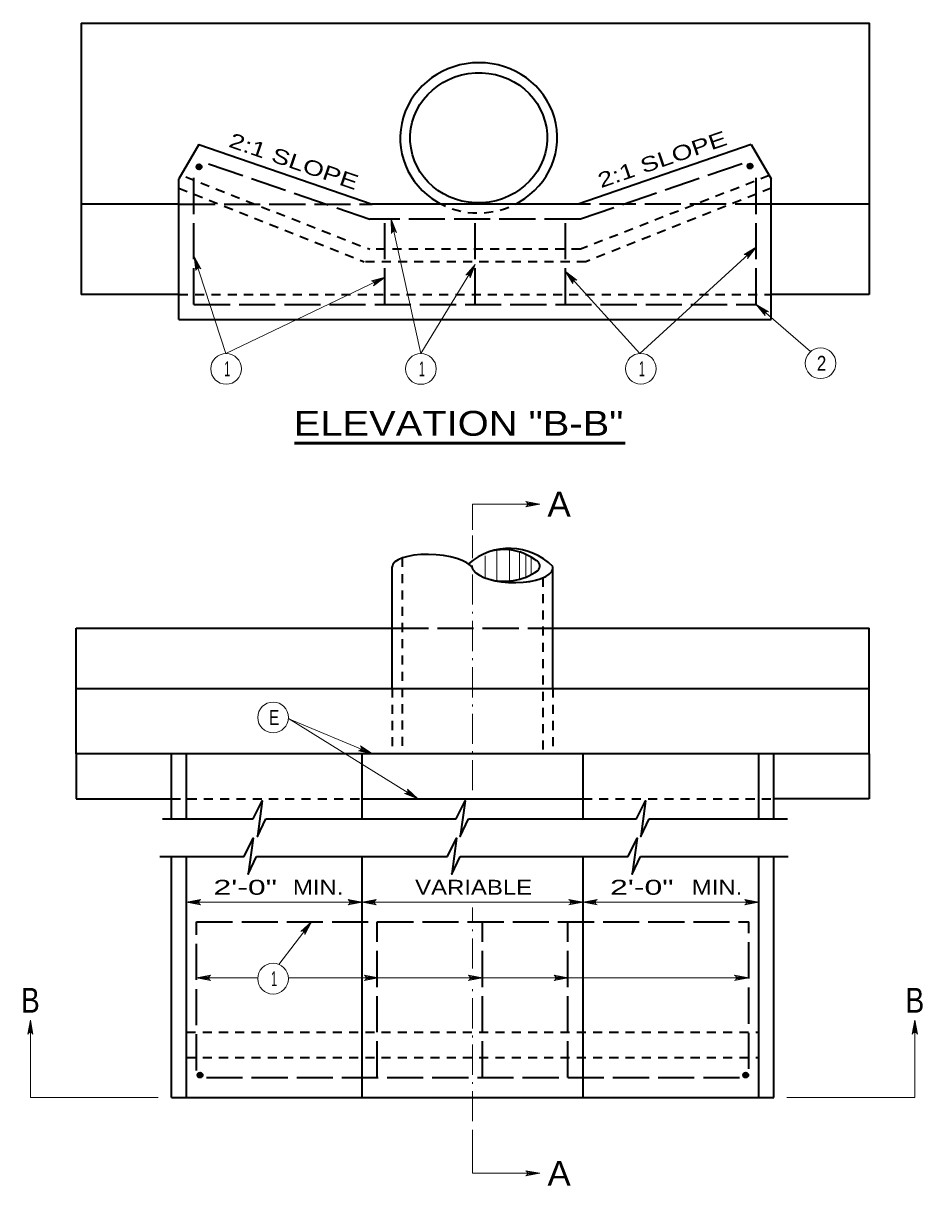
# Model space of a CAD drawing. Extents: x 2 to 114, y -129 to 32.
# Drawn here: x 1.8 to 61.5, y -49.3 to 27.9 of the extents above; entities that cross this region are included whole.
import ezdxf
from ezdxf.enums import TextEntityAlignment as Align

# ---------------------------------------------------------------- set-up
doc = ezdxf.new("R2010")
doc.units = 0
doc.header["$LTSCALE"] = 0.4
for name, pattern in [('DOT_DASHED', [7.7, 5, -1.2, 0.3, -1.2]), ('LONG_DASHED', [7.5, 6, -1.5]), ('SHORT_DASHED', [2.7, 1.5, -1.2])]:
    doc.linetypes.add(name, pattern=pattern)
for name, color, linetype, lineweight in [('1', 7, 'Continuous', 35), ('10', 7, 'Continuous', 13), ('12', 7, 'Continuous', 53), ('13', 7, 'Continuous', 25), ('6', 7, 'Continuous', 13)]:
    doc.layers.add(name, color=color, linetype=linetype, lineweight=lineweight)

msp = doc.modelspace()

# ---------------------------------------------------------------- linework, layer by layer
at = {"layer": '1'}
for p, q in [((5.5976, 27.8637), (5.5976, 9.8637)), ((13.4219, 19.8096), (12.0976, 17.5303)), ((13.4219, 19.8096), (24.9309, 15.8637)), ((50.1066, 19.8096), (38.5976, 15.8637)), ((50.1066, 19.8096), (51.4309, 17.5303)), ((12.0976, 8.197), (12.0976, 17.5303)), ((51.4309, 8.197), (51.4309, 17.5303)), ((12.0976, 15.8637), (5.5976, 15.8637)), ((38.7681, 15.8637), (24.9309, 15.8637)), ((57.9309, 15.8637), (51.4309, 15.8637)), ((51.4309, 9.8637), (51.4309, 14.8637)), ((12.0976, 9.8637), (5.5976, 9.8637)), ((57.9309, 9.8637), (51.4309, 9.8637)), ((12.0976, 8.197), (51.4309, 8.197)), ((26.2643, -16.2894), (26.2643, -8.1969)), ((31.6675, -8.4378), (31.5976, -8.3026)), ((36.9309, -16.2894), (36.9309, -8.1969)), ((5.2643, -16.2894), (5.2643, -12.2894)), ((5.2643, -12.2894), (26.2643, -12.2894)), ((36.9309, -12.2894), (57.9309, -12.2894)), ((57.9309, -16.2894), (57.9309, -12.2894)), ((5.2643, -16.2894), (57.9309, -16.2894)), ((5.2643, -20.6228), (5.2643, -16.2894)), ((57.9309, -20.6228), (57.9309, -16.2894)), ((11.5976, -20.6228), (5.2643, -20.6228)), ((5.2643, -20.6228), (5.2643, -23.6228)), ((11.5976, -24.9561), (11.5976, -20.6228)), ((51.5976, -20.6228), (11.5976, -20.6228)), ((12.5976, -24.9561), (12.5976, -20.6228)), ((24.2643, -24.9561), (24.2643, -20.6228)), ((38.9309, -24.9561), (38.9309, -20.6228)), ((50.5976, -24.9561), (50.5976, -20.6228)), ((51.5976, -24.9561), (51.5976, -20.6228)), ((57.9309, -20.6228), (51.5976, -20.6228)), ((57.9309, -20.6228), (57.9309, -23.6228)), ((5.2643, -23.6228), (11.5976, -23.6228)), ((24.2643, -23.6228), (38.9309, -23.6228)), ((24.2643, -23.6228), (38.9309, -23.6228)), ((57.9309, -23.6228), (51.5976, -23.6228)), ((10.999, -24.9561), (17.0348, -24.9561)), ((17.8594, -24.9561), (30.5059, -24.9561)), ((31.3306, -24.9561), (42.49, -24.9561)), ((43.3146, -24.9561), (52.5059, -24.9561)), ((10.8241, -27.4473), (16.4224, -27.4473)), ((11.5976, -43.4473), (11.5976, -27.4473)), ((12.5976, -43.4473), (12.5976, -27.4473)), ((17.2471, -27.4473), (29.9373, -27.4473)), ((24.2643, -43.4473), (24.2643, -27.4473)), ((30.762, -27.4473), (41.9214, -27.4473)), ((38.9309, -43.4473), (38.9309, -27.4473)), ((42.746, -27.4473), (52.5496, -27.4473)), ((50.5976, -43.4473), (50.5976, -27.4473)), ((51.5976, -43.4473), (51.5976, -27.4473)), ((11.5976, -43.4473), (51.5976, -43.4473))]:
    msp.add_line(p, q, dxfattribs=at)
at = {"layer": '1', "linetype": 'LONG_DASHED'}
for p, q in [((14.0701, 18.5302), (24.7643, 14.8637)), ((49.4889, 18.5407), (38.7643, 14.8637)), ((13.0976, 9.197), (13.0976, 17.7631)), ((50.4309, 9.197), (50.4309, 18.0603)), ((12.0976, 15.8637), (24.9309, 15.8637)), ((51.4309, 15.8637), (38.7681, 15.8637)), ((38.7643, 14.8637), (24.7643, 14.8637)), ((25.7643, 9.197), (25.7643, 14.8637)), ((31.7643, 9.197), (31.7643, 14.8637)), ((37.7643, 9.197), (37.7643, 14.8637)), ((13.0976, 9.197), (50.4309, 9.197)), ((26.2643, -12.2894), (36.9309, -12.2894)), ((13.2643, -31.7806), (49.9309, -31.7806)), ((13.2643, -41.642), (13.2643, -31.7806)), ((25.2643, -42.114), (25.2643, -31.7806)), ((32.2643, -42.114), (32.2643, -31.7806)), ((37.9309, -42.114), (37.9309, -31.7806)), ((49.9309, -41.5423), (49.9309, -31.7806)), ((13.9208, -42.114), (49.3179, -42.114))]:
    msp.add_line(p, q, dxfattribs=at)
at = {"layer": '1', "linetype": 'SHORT_DASHED'}
for p, q in [((51.3017, 17.7527), (38.7643, 12.8637)), ((12.548, 17.6583), (24.7643, 12.8637)), ((12.0976, 16.916), (24.4031, 12.0303)), ((51.4309, 16.916), (39.1254, 12.0303)), ((38.7643, 12.8637), (24.7643, 12.8637)), ((39.1254, 12.0303), (24.4031, 12.0303)), ((12.0976, 9.8637), (51.4309, 9.8637)), ((26.9309, -7.6253), (26.9309, -20.6228)), ((36.2643, -8.9469), (36.2643, -20.6228)), ((26.2643, -16.2894), (26.2643, -20.6228)), ((36.9309, -16.2894), (36.9309, -20.6228)), ((11.5976, -23.6228), (24.2643, -23.6228)), ((38.9309, -23.6228), (51.5976, -23.6228)), ((12.5976, -39.114), (50.5976, -39.114)), ((12.5976, -40.7806), (50.5976, -40.7806))]:
    msp.add_line(p, q, dxfattribs=at)
at = {"layer": '1'}
msp.add_lwpolyline([(5.5976, 27.8637), (57.9309, 27.8637), (57.9309, 9.8637)], dxfattribs=at)
for centre, radius in [((50.0237, 18.3857), 0.1667), ((13.4364, 18.3326), 0.1667), ((13.4364, 18.3326), 0.125), ((13.4364, 18.3326), 0.0833), ((13.4364, 18.3326), 0.0417), ((50.0237, 18.3857), 0.125), ((50.0237, 18.3857), 0.0833), ((50.0237, 18.3857), 0.0417), ((13.5012, -41.9572), 0.1667), ((13.5012, -41.9572), 0.125), ((13.5012, -41.9572), 0.0833), ((13.5012, -41.9572), 0.0417), ((49.7375, -41.9572), 0.1667), ((49.7375, -41.9572), 0.125), ((49.7375, -41.9572), 0.0833), ((49.7375, -41.9572), 0.0417)]:
    msp.add_circle(centre, radius, dxfattribs=at)
for centre, radius, start, end in [((34.034, -11.1003), 4.1015, 45.06377, 131.36728), ((33.6786, -10.6189), 3.5429, 52.80449, 103.76963), ((33.7104, -5.3561), 3.82, 253.17764, 305.12429), ((35.6608, -8.1634), 0.3998, 313.54691, 66.48149)]:
    msp.add_arc(centre, radius, start, end, dxfattribs=at)
for centre, major_axis, ratio, start_param, end_param in [((32.0041, 20.2567), (-5.2068, -0.2894), 0.95662, 2.0626148, 7.2453181), ((28.957, -8.3542), (2.6927, -0.1573), 0.351288, 0.2186166, 3.1826279), ((34.2678, -8.2376), (2.6702, -0.0408), 0.385255, 3.3768954, 6.2157676)]:
    msp.add_ellipse(centre, major_axis=major_axis, ratio=ratio, start_param=start_param, end_param=end_param, dxfattribs=at)
msp.add_ellipse((32.0041, 20.2567), major_axis=(-4.5412, -0.2524), ratio=0.950261, dxfattribs=at)
at = {"layer": '1', "linetype": 'SHORT_DASHED'}
msp.add_ellipse((32.0041, 20.2567), major_axis=(-5.2068, -0.2894), ratio=0.95662, start_param=0.9621318, end_param=2.0626168, dxfattribs=at)
at = {"layer": '10'}
for p, q in [((15.2195, 5.9356), (13.1063, 12.3876)), ((42.7045, 5.9313), (50.4309, 13.0053)), ((15.2104, 5.9313), (25.7913, 11.0041)), ((42.709, 5.9354), (37.7643, 11.39)), ((50.4309, 9.197), (54.0407, 6.068)), ((31.5976, -4.0563), (36.0703, -4.0563)), ((31.5976, -5.7715), (31.5976, -4.0563)), ((19.3702, -18.2923), (27.9716, -23.6164)), ((19.4419, -18.3367), (24.9465, -20.6262)), ((18.722, -34.6078), (20.8929, -31.7806)), ((13.2643, -35.5077), (17.3297, -35.5077)), ((19.3657, -35.5077), (49.9309, -35.5077)), ((2.231, -43.4473), (2.231, -38.3153)), ((60.9642, -43.4473), (60.9642, -38.3153)), ((10.7147, -43.4473), (2.231, -43.4473)), ((60.9642, -43.4473), (52.4661, -43.4473)), ((31.5976, -48.476), (31.5976, -45.5984)), ((31.5976, -48.476), (36.0703, -48.476))]:
    msp.add_line(p, q, dxfattribs=at)
at = {"layer": '10', "linetype": 'DOT_DASHED'}
for p, q in [((31.5976, -23.0458), (31.5976, -6.1362)), ((31.5976, -34.8878), (31.5976, -30.8354)), ((31.5976, -45.0148), (31.5976, -36.128))]:
    msp.add_line(p, q, dxfattribs=at)
at = {"layer": '10'}
for points in [[(26.182, 14.8538), (28.1659, 5.9313), (31.7731, 11.8462)], [(26.182, 14.8538), (26.5549, 13.9819), (26.4908, 14.0412), (26.4217, 14.0637), (26.3584, 14.0606), (26.2997, 14.0366), (26.2467, 13.9869), (26.2137, 13.906), (26.182, 14.8538), (26.2467, 13.9869), (26.2997, 14.0366), (26.182, 14.8538), (26.3584, 14.0606), (26.4217, 14.0637), (26.182, 14.8538), (26.4908, 14.0412)], [(13.1063, 12.3876), (13.5625, 11.5562), (13.4928, 11.609), (13.4219, 11.6247), (13.3592, 11.6154), (13.3031, 11.5858), (13.2552, 11.5311), (13.2303, 11.4474), (13.1063, 12.3876), (13.2552, 11.5311), (13.3031, 11.5858), (13.1063, 12.3876), (13.3592, 11.6154), (13.4219, 11.6247), (13.1063, 12.3876), (13.4928, 11.609)], [(50.4309, 13.0053), (49.8615, 12.247), (49.8809, 12.3322), (49.866, 12.4033), (49.8317, 12.4566), (49.7816, 12.4955), (49.712, 12.5166), (49.6255, 12.5048), (50.4309, 13.0053), (49.712, 12.5166), (49.7816, 12.4955), (50.4309, 13.0053), (49.8317, 12.4566), (49.866, 12.4033), (50.4309, 13.0053), (49.8809, 12.3322)], [(31.7731, 11.8462), (31.437, 10.9594), (31.4319, 11.0467), (31.3978, 11.1108), (31.35, 11.1525), (31.2911, 11.1759), (31.2184, 11.1768), (31.1386, 11.1414), (31.7731, 11.8462), (31.2184, 11.1768), (31.2911, 11.1759), (31.7731, 11.8462), (31.35, 11.1525), (31.3978, 11.1108), (31.7731, 11.8462), (31.4319, 11.0467)], [(25.7913, 11.0041), (25.0263, 10.4436), (25.0696, 10.5195), (25.076, 10.5918), (25.0586, 10.6528), (25.0219, 10.7046), (24.9615, 10.7449), (24.8752, 10.7587), (25.7913, 11.0041), (24.9615, 10.7449), (25.0219, 10.7046), (25.7913, 11.0041), (25.0586, 10.6528), (25.076, 10.5918), (25.7913, 11.0041), (25.0696, 10.5195)], [(37.7643, 11.39), (38.5198, 10.8168), (38.4346, 10.8366), (38.3635, 10.8221), (38.31, 10.788), (38.2709, 10.7381), (38.2494, 10.6687), (38.2608, 10.5821), (37.7643, 11.39), (38.2494, 10.6687), (38.2709, 10.7381), (37.7643, 11.39), (38.31, 10.788), (38.3635, 10.8221), (37.7643, 11.39), (38.4346, 10.8366)], [(50.4309, 9.197), (51.2497, 8.7185), (51.1628, 8.728), (51.0939, 8.705), (51.0449, 8.6648), (51.012, 8.6106), (50.9991, 8.5391), (51.0208, 8.4544), (50.4309, 9.197), (50.9991, 8.5391), (51.012, 8.6106), (50.4309, 9.197), (51.0449, 8.6648), (51.0939, 8.705), (50.4309, 9.197), (51.1628, 8.728)], [(36.0703, -4.0563), (35.1382, -4.2311), (35.21, -4.1813), (35.2471, -4.1188), (35.2578, -4.0563), (35.2471, -3.9938), (35.21, -3.9313), (35.1382, -3.8815), (36.0703, -4.0563), (35.21, -3.9313), (35.2471, -3.9938), (36.0703, -4.0563), (35.2578, -4.0563), (35.2471, -4.1188), (36.0703, -4.0563), (35.21, -4.1813)], [(24.9465, -20.6262), (24.0188, -20.4296), (24.1042, -20.4112), (24.1624, -20.3677), (24.1963, -20.3141), (24.2104, -20.2523), (24.2002, -20.1804), (24.153, -20.1069), (24.9465, -20.6262), (24.2002, -20.1804), (24.2104, -20.2523), (24.9465, -20.6262), (24.1963, -20.3141), (24.1624, -20.3677), (24.9465, -20.6262), (24.1042, -20.4112)], [(27.9716, -23.6164), (27.087, -23.2745), (27.1743, -23.2699), (27.2387, -23.2363), (27.2807, -23.1888), (27.3045, -23.13), (27.3059, -23.0574), (27.271, -22.9773), (27.9716, -23.6164), (27.3059, -23.0574), (27.3045, -23.13), (27.9716, -23.6164), (27.2807, -23.1888), (27.2387, -23.2363), (27.9716, -23.6164), (27.1743, -23.2699)], [(12.5976, -30.4844), (13.5297, -30.3096), (13.4579, -30.3594), (13.4208, -30.4219), (13.4101, -30.4844), (13.4208, -30.5469), (13.4579, -30.6094), (13.5297, -30.6591), (12.5976, -30.4844), (13.4579, -30.6094), (13.4208, -30.5469), (12.5976, -30.4844), (13.4101, -30.4844), (13.4208, -30.4219), (12.5976, -30.4844), (13.4579, -30.3594)], [(12.5976, -30.4844), (24.2643, -30.4844), (38.9309, -30.4844), (50.5976, -30.4844)], [(24.2643, -30.4844), (23.3322, -30.6591), (23.404, -30.6094), (23.4411, -30.5469), (23.4518, -30.4844), (23.4411, -30.4219), (23.404, -30.3594), (23.3322, -30.3096), (24.2643, -30.4844), (23.404, -30.3594), (23.4411, -30.4219), (24.2643, -30.4844), (23.4518, -30.4844), (23.4411, -30.5469), (24.2643, -30.4844), (23.404, -30.6094)], [(24.2643, -30.4844), (25.1963, -30.6591), (25.1245, -30.6094), (25.0875, -30.5469), (25.0768, -30.4844), (25.0875, -30.4219), (25.1245, -30.3594), (25.1963, -30.3096), (24.2643, -30.4844), (25.1245, -30.3594), (25.0875, -30.4219), (24.2643, -30.4844), (25.0768, -30.4844), (25.0875, -30.5469), (24.2643, -30.4844), (25.1245, -30.6094)], [(38.9309, -30.4844), (37.9989, -30.6591), (38.0707, -30.6094), (38.1077, -30.5469), (38.1184, -30.4844), (38.1077, -30.4219), (38.0707, -30.3594), (37.9989, -30.3096), (38.9309, -30.4844), (38.0707, -30.3594), (38.1077, -30.4219), (38.9309, -30.4844), (38.1184, -30.4844), (38.1077, -30.5469), (38.9309, -30.4844), (38.0707, -30.6094)], [(38.9309, -30.4844), (39.863, -30.6591), (39.7912, -30.6094), (39.7542, -30.5469), (39.7434, -30.4844), (39.7542, -30.4219), (39.7912, -30.3594), (39.863, -30.3096), (38.9309, -30.4844), (39.7912, -30.3594), (39.7542, -30.4219), (38.9309, -30.4844), (39.7434, -30.4844), (39.7542, -30.5469), (38.9309, -30.4844), (39.7912, -30.6094)], [(50.5976, -30.4844), (49.6655, -30.6591), (49.7374, -30.6094), (49.7744, -30.5469), (49.7851, -30.4844), (49.7744, -30.4219), (49.7374, -30.3594), (49.6655, -30.3096), (50.5976, -30.4844), (49.7374, -30.3594), (49.7744, -30.4219), (50.5976, -30.4844), (49.7851, -30.4844), (49.7744, -30.5469), (50.5976, -30.4844), (49.7374, -30.6094)], [(20.8929, -31.7806), (20.4639, -32.6263), (20.4681, -32.5391), (20.4411, -32.4716), (20.3981, -32.4251), (20.342, -32.3955), (20.2699, -32.3868), (20.1867, -32.4135), (20.8929, -31.7806), (20.2699, -32.3868), (20.342, -32.3955), (20.8929, -31.7806), (20.3981, -32.4251), (20.4411, -32.4716), (20.8929, -31.7806), (20.4681, -32.5391)], [(13.2643, -35.5077), (14.1963, -35.333), (14.1245, -35.3827), (14.0875, -35.4452), (14.0768, -35.5077), (14.0875, -35.5702), (14.1245, -35.6327), (14.1963, -35.6825), (13.2643, -35.5077), (14.1245, -35.6327), (14.0875, -35.5702), (13.2643, -35.5077), (14.0768, -35.5077), (14.0875, -35.4452), (13.2643, -35.5077), (14.1245, -35.3827)], [(25.3505, -35.5077), (24.4184, -35.6825), (24.4902, -35.6327), (24.5273, -35.5702), (24.538, -35.5077), (24.5273, -35.4452), (24.4902, -35.3827), (24.4184, -35.333), (25.3505, -35.5077), (24.4902, -35.3827), (24.5273, -35.4452), (25.3505, -35.5077), (24.538, -35.5077), (24.5273, -35.5702), (25.3505, -35.5077), (24.4902, -35.6327)], [(32.261, -35.5077), (31.3289, -35.6825), (31.4008, -35.6327), (31.4378, -35.5702), (31.4485, -35.5077), (31.4378, -35.4452), (31.4008, -35.3827), (31.3289, -35.333), (32.261, -35.5077), (31.4008, -35.3827), (31.4378, -35.4452), (32.261, -35.5077), (31.4485, -35.5077), (31.4378, -35.5702), (32.261, -35.5077), (31.4008, -35.6327)], [(37.9469, -35.5077), (37.0148, -35.6825), (37.0866, -35.6327), (37.1237, -35.5702), (37.1344, -35.5077), (37.1237, -35.4452), (37.0866, -35.3827), (37.0148, -35.333), (37.9469, -35.5077), (37.0866, -35.3827), (37.1237, -35.4452), (37.9469, -35.5077), (37.1344, -35.5077), (37.1237, -35.5702), (37.9469, -35.5077), (37.0866, -35.6327)], [(49.9309, -35.5077), (48.9989, -35.6825), (49.0707, -35.6327), (49.1077, -35.5702), (49.1184, -35.5077), (49.1077, -35.4452), (49.0707, -35.3827), (48.9989, -35.333), (49.9309, -35.5077), (49.0707, -35.3827), (49.1077, -35.4452), (49.9309, -35.5077), (49.1184, -35.5077), (49.1077, -35.5702), (49.9309, -35.5077), (49.0707, -35.6327)], [(2.231, -38.3153), (2.4058, -39.2474), (2.356, -39.1755), (2.2935, -39.1385), (2.231, -39.1278), (2.1685, -39.1385), (2.106, -39.1755), (2.0563, -39.2474), (2.231, -38.3153), (2.106, -39.1755), (2.1685, -39.1385), (2.231, -38.3153), (2.231, -39.1278), (2.2935, -39.1385), (2.231, -38.3153), (2.356, -39.1755)], [(60.9642, -38.3153), (61.1389, -39.2474), (61.0892, -39.1755), (61.0267, -39.1385), (60.9642, -39.1278), (60.9017, -39.1385), (60.8392, -39.1755), (60.7894, -39.2474), (60.9642, -38.3153), (60.8392, -39.1755), (60.9017, -39.1385), (60.9642, -38.3153), (60.9642, -39.1278), (61.0267, -39.1385), (60.9642, -38.3153), (61.0892, -39.1755)], [(36.0703, -48.476), (35.1382, -48.6507), (35.21, -48.601), (35.2471, -48.5385), (35.2578, -48.476), (35.2471, -48.4135), (35.21, -48.351), (35.1382, -48.3012), (36.0703, -48.476), (35.21, -48.351), (35.2471, -48.4135), (36.0703, -48.476), (35.2578, -48.476), (35.2471, -48.5385), (36.0703, -48.476), (35.21, -48.601)]]:
    msp.add_lwpolyline(points, dxfattribs=at)
at = {"layer": '10', "lineweight": 35}
for points in [[(17.0348, -24.9561), (17.6296, -23.7407), (17.3061, -26.1194), (17.8594, -24.9561)], [(30.5059, -24.9561), (31.1007, -23.7407), (30.7772, -26.1194), (31.3306, -24.9561)], [(42.49, -24.9561), (43.0848, -23.7407), (42.7613, -26.1194), (43.3146, -24.9561)], [(16.4224, -27.4473), (17.0173, -26.2319), (16.6938, -28.6106), (17.2471, -27.4473)], [(29.9373, -27.4473), (30.5321, -26.2319), (30.2086, -28.6106), (30.762, -27.4473)], [(41.9214, -27.4473), (42.5162, -26.2319), (42.1927, -28.6106), (42.746, -27.4473)]]:
    msp.add_lwpolyline(points, dxfattribs=at)
at = {"layer": '10'}
for centre in [(54.7023, 5.2927), (15.2319, 4.92), (28.1652, 4.9154), (42.77, 4.931), (18.3535, -18.2169), (18.3477, -35.5558)]:
    msp.add_circle(centre, 1.0192, dxfattribs=at)
at = {"layer": '12'}
msp.add_line((19.7697, -0.0179), (41.7238, -0.0179), dxfattribs=at)
at = {"layer": '6'}
for p, q in [((32.4304, -7.4886), (32.4304, -8.9604)), ((33.2176, -7.0809), (33.2176, -9.17)), ((34.0486, -6.9988), (34.0486, -9.2602)), ((34.7047, -7.2279), (34.7047, -9.0444)), ((35.1421, -7.3924), (35.1421, -8.8977)), ((35.492, -7.5753), (35.492, -8.7352))]:
    msp.add_line(p, q, dxfattribs=at)
msp.add_lwpolyline([(33.5303, -9.1836), (33.765, -9.1909), (34.0291, -9.1762), (34.3151, -9.1396), (34.6672, -9.0662), (35.1146, -8.9341), (35.6574, -8.6699), (35.9068, -8.5084), (36.0242, -8.369), (36.0902, -8.1782), (36.0828, -8.0754), (36.0168, -7.9506), (35.9141, -7.8259), (35.7454, -7.7158), (35.5034, -7.5544), (35.078, -7.3342), (34.7992, -7.2314), (34.4985, -7.1507), (34.1464, -7.0847), (33.8017, -7.0406), (33.5156, -7.048), (34.0951, -7.0113), (34.5352, -7.0406), (34.8579, -7.0993), (35.342, -7.2168), (35.7674, -7.4002), (36.1122, -7.5764), (36.4789, -7.8186), (36.7796, -8.0607), (36.897, -8.1928), (36.919, -8.2369), (36.897, -8.3983), (36.787, -8.5745), (36.6476, -8.6992), (36.3909, -8.8607), (35.9948, -9.0148), (35.5767, -9.1322), (35.0266, -9.2056), (34.6305, -9.2423), (34.1831, -9.235)], close=True, dxfattribs=at)

# ---------------------------------------------------------------- texts
at = {"layer": '12', "width": 1.35}
for rotation, p in [(341.075, (19.5649, 18.232)), (18.925, (44.3505, 18.3646))]:
    msp.add_text('2:1 SLOPE', height=0.99, rotation=rotation, dxfattribs=at).set_placement(p, align=Align.CENTER)
at = {"layer": '12'}
for s, height, width, p in [('ELEVATION "B-B"', 1.65, 1.2, (30.666, 0.4821)), ('MIN.', 0.99, 1.2, (21.341, -29.9844)), ('VARIABLE', 0.99, 1.2, (31.6672, -29.9844)), ('MIN.', 0.99, 1.2, (47.8338, -29.9844)), ('B', 1.65, 0.85, (2.231, -37.8153)), ('B', 1.65, 0.85, (60.9642, -37.8153))]:
    msp.add_text(s, height=height, dxfattribs=dict(at, width=width)).set_placement(p, align=Align.CENTER)
at = {"layer": '12', "width": 1.05}
for p in [(36.5703, -4.8813), (36.5703, -49.301)]:
    msp.add_text('A', height=1.65, dxfattribs=at).set_placement(p)
at = {"layer": '13'}
for s, width, p in [('1', 0.55, (15.3015, 4.425)), ('1', 0.55, (28.2347, 4.4204)), ('1', 0.55, (42.8396, 4.436)), ('2', 0.85, (54.7718, 4.7977)), ('E', 0.75, (18.423, -18.7119)), ('2\'-0"', 1.6, (16.5005, -29.9844)), ('2\'-0"', 1.6, (42.8338, -29.9844)), ('1', 0.55, (18.4173, -36.0508))]:
    msp.add_text(s, height=0.99, dxfattribs=dict(at, width=width)).set_placement(p, align=Align.CENTER)

doc.saveas('drawing.dxf')
